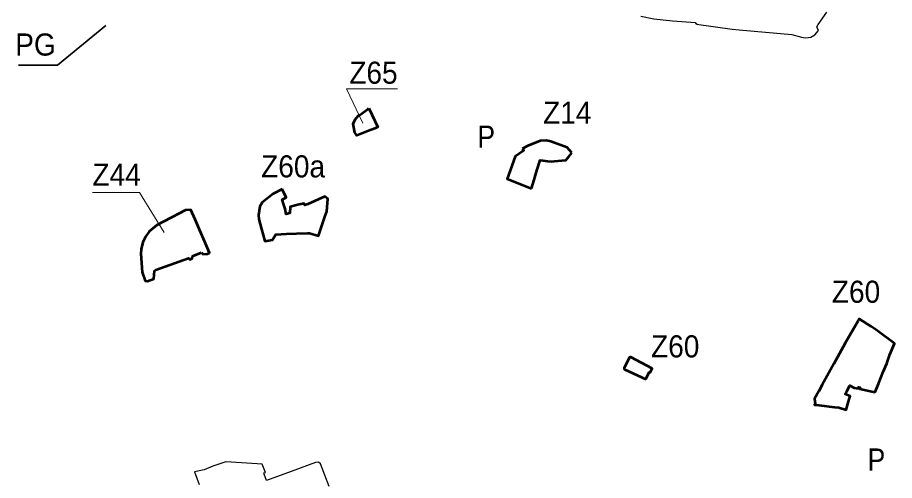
# Model space of a CAD drawing. Extents: x -650246 to -642674, y -1074280 to -1066767.
# Drawn here: x -647715 to -646763, y -1070690 to -1070187 of the extents above; entities that cross this region are included whole.
import ezdxf

# ---------------------------------------------------------------- set-up
doc = ezdxf.new("R2010")
doc.units = 0
doc.header["$LTSCALE"] = 9.6
for name, color, linetype, lineweight in [('42', 7, 'Continuous', 25), ('45', 7, 'Continuous', 53), ('46', 7, 'Continuous', 13), ('60', 7, 'Continuous', 35)]:
    doc.layers.add(name, color=color, linetype=linetype, lineweight=lineweight)

msp = doc.modelspace()

# ---------------------------------------------------------------- linework, layer by layer
at = {"layer": '42'}
for points in [[(-647038.31, -1070185.73), (-647024.2, -1070188.68), (-647003.89, -1070190.89), (-646978.73, -1070192.54), (-646978.72, -1070193.6), (-646977.7, -1070193.62), (-646977.7, -1070194.45), (-646938.98, -1070199.89), (-646931.25, -1070200.56), (-646874.04, -1070205.5), (-646863.66, -1070208.37), (-646859.54, -1070209.09), (-646853.67, -1070208.44), (-646849.15, -1070205.9), (-646845.3, -1070201.3), (-646847.17, -1070197.38), (-646845.76, -1070194.67), (-646836.06, -1070181.31)], [(-647377.04, -1070696.22), (-647386.39, -1070671.74), (-647388.31, -1070669.95), (-647391.74, -1070670.16), (-647418.28, -1070679.89), (-647444.78, -1070689.6), (-647447.31, -1070682.72), (-647447.76, -1070681.5), (-647446.22, -1070680.91), (-647447.58, -1070677.36), (-647449.69, -1070671.81), (-647455.17, -1070671.48), (-647489.21, -1070669.41), (-647496.64, -1070671.93), (-647503.3, -1070674.3), (-647512.51, -1070677.98), (-647523.27, -1070680.11), (-647518.19, -1070693.93)]]:
    msp.add_lwpolyline(points, dxfattribs=at)
at = {"layer": '45'}
for points in [[(-647333.87, -1070285.66), (-647324.11, -1070306.21), (-647324.94, -1070306.63), (-647327.18, -1070307.52), (-647333.97, -1070310.22), (-647346.97, -1070315.05), (-647349, -1070312), (-647350.67, -1070302.55), (-647348.677, -1070297.894), (-647345.27, -1070293.99), (-647343.9, -1070292.96), (-647337.56, -1070288.43), (-647334.91, -1070286.51)], [(-647333.87, -1070285.66), (-647324.11, -1070306.21), (-647324.94, -1070306.63), (-647327.18, -1070307.52), (-647333.97, -1070310.22), (-647346.97, -1070315.05), (-647349, -1070312), (-647350.67, -1070302.55), (-647348.677, -1070297.894), (-647345.27, -1070293.99), (-647343.9, -1070292.96), (-647337.56, -1070288.43), (-647334.91, -1070286.51)], [(-647427.8, -1070373.32), (-647437.76, -1070378.66), (-647449.69, -1070387.83), (-647452.17, -1070392.38), (-647453.71, -1070401.81), (-647453.35, -1070406.09), (-647450.51, -1070416.96), (-647446.93, -1070429.99), (-647438.45, -1070428.47), (-647434.85, -1070422.64), (-647423.38, -1070421.87), (-647412.51, -1070421.5), (-647400.41, -1070421.08), (-647398.21, -1070421.15), (-647388.6, -1070424.24), (-647381.11, -1070402.45), (-647379.3, -1070397.57), (-647378.49, -1070383.91), (-647381.65, -1070381.45), (-647400.22, -1070389.64), (-647403.27, -1070390.91), (-647404, -1070388.84), (-647409.36, -1070390.24), (-647419.08, -1070392.52), (-647419.68, -1070399.59), (-647423.58, -1070400.59), (-647424.54, -1070394.78), (-647425.99, -1070390.47), (-647427.96, -1070384.64), (-647423.57, -1070382.64)], [(-647427.8, -1070373.32), (-647437.76, -1070378.66), (-647449.69, -1070387.83), (-647452.17, -1070392.38), (-647453.71, -1070401.81), (-647453.35, -1070406.09), (-647450.51, -1070416.96), (-647446.93, -1070429.99), (-647438.45, -1070428.47), (-647434.85, -1070422.64), (-647423.38, -1070421.87), (-647412.51, -1070421.5), (-647400.41, -1070421.08), (-647398.21, -1070421.15), (-647388.6, -1070424.24), (-647381.11, -1070402.45), (-647379.3, -1070397.57), (-647378.49, -1070383.91), (-647381.65, -1070381.45), (-647400.22, -1070389.64), (-647403.27, -1070390.91), (-647404, -1070388.84), (-647409.36, -1070390.24), (-647419.08, -1070392.52), (-647419.68, -1070399.59), (-647423.58, -1070400.59), (-647424.54, -1070394.78), (-647425.99, -1070390.47), (-647427.96, -1070384.64), (-647423.57, -1070382.64)], [(-647515.73, -1070442.32), (-647514.23, -1070444.18), (-647509.22, -1070443.62), (-647506.95, -1070442.71), (-647522.54, -1070406.51), (-647527.1, -1070395.72), (-647533.1, -1070396.26), (-647564.01, -1070412.59), (-647572.37, -1070419.41), (-647576.48, -1070425.09), (-647579.22, -1070431.05), (-647581.04, -1070438.4), (-647581.54, -1070443.7), (-647580.1, -1070463.69), (-647576.92, -1070473), (-647574.28, -1070473.46), (-647567.32, -1070470.66), (-647566.55, -1070462.22), (-647565.11, -1070461.12), (-647529.74, -1070448.27), (-647528.28, -1070449.87), (-647525.54, -1070448.89), (-647525.45, -1070446.21)], [(-647515.73, -1070442.32), (-647514.23, -1070444.18), (-647509.22, -1070443.62), (-647506.95, -1070442.71), (-647522.54, -1070406.51), (-647527.1, -1070395.72), (-647533.1, -1070396.26), (-647564.01, -1070412.59), (-647572.37, -1070419.41), (-647576.48, -1070425.09), (-647579.22, -1070431.05), (-647581.04, -1070438.4), (-647581.54, -1070443.7), (-647580.1, -1070463.69), (-647576.92, -1070473), (-647574.28, -1070473.46), (-647567.32, -1070470.66), (-647566.55, -1070462.22), (-647565.11, -1070461.12), (-647529.74, -1070448.27), (-647528.28, -1070449.87), (-647525.54, -1070448.89), (-647525.45, -1070446.21)], [(-646802.19, -1070516.26), (-646816.42, -1070540.49), (-646828.45, -1070562.89), (-646841.16, -1070585.79), (-646844.76, -1070592.54), (-646849.72, -1070600.98), (-646848.99, -1070606.28), (-646849.59, -1070607.4), (-646844.96, -1070607.98), (-646827.88, -1070610.12), (-646822.99, -1070610.51), (-646815.05, -1070613.14), (-646812.5, -1070603.78), (-646811.5, -1070600.29), (-646810.82, -1070598.23), (-646816.11, -1070595.8), (-646814.52, -1070592.78), (-646811.06, -1070586.67), (-646806.41, -1070589), (-646802.06, -1070589.93), (-646801.73, -1070588.37), (-646800.13, -1070588.71), (-646800.47, -1070590.28), (-646784.18, -1070593.76), (-646784, -1070593.34), (-646783.59, -1070593.52), (-646779.9, -1070584.92), (-646774.91, -1070571.88), (-646771.17, -1070562.7), (-646767.63, -1070553.09), (-646762.71, -1070540.85), (-646782.63, -1070526.02), (-646788, -1070522.49), (-646800.94, -1070514.04)], [(-646802.19, -1070516.26), (-646816.42, -1070540.49), (-646828.45, -1070562.89), (-646841.16, -1070585.79), (-646844.76, -1070592.54), (-646849.72, -1070600.98), (-646848.99, -1070606.28), (-646849.59, -1070607.4), (-646844.96, -1070607.98), (-646827.88, -1070610.12), (-646822.99, -1070610.51), (-646815.05, -1070613.14), (-646812.5, -1070603.78), (-646811.5, -1070600.29), (-646810.82, -1070598.23), (-646816.11, -1070595.8), (-646814.52, -1070592.78), (-646811.06, -1070586.67), (-646806.41, -1070589), (-646802.06, -1070589.93), (-646801.73, -1070588.37), (-646800.13, -1070588.71), (-646800.47, -1070590.28), (-646784.18, -1070593.76), (-646784, -1070593.34), (-646783.59, -1070593.52), (-646779.9, -1070584.92), (-646774.91, -1070571.88), (-646771.17, -1070562.7), (-646767.63, -1070553.09), (-646762.71, -1070540.85), (-646782.63, -1070526.02), (-646788, -1070522.49), (-646800.94, -1070514.04)], [(-647032.738, -1070579.83), (-647029.168, -1070572.13), (-647028.248, -1070572.63), (-647025.868, -1070568.26), (-647049.248, -1070555.64), (-647050.098, -1070555.74), (-647050.868, -1070556.59), (-647052.498, -1070559.7), (-647056.518, -1070567.41), (-647056.528, -1070568.32), (-647055.518, -1070569.07)]]:
    msp.add_lwpolyline(points, close=True, dxfattribs=at)
for points in [[(-647113.37, -1070333.96), (-647118.28, -1070328.29), (-647135.94, -1070321.54), (-647140.83, -1070320.47), (-647147.66, -1070321.04), (-647161.17, -1070326.29), (-647167.03, -1070329.81)], [(-647167.03, -1070329.81), (-647165.36, -1070331.59), (-647174.81, -1070338.01), (-647183.55, -1070362.35), (-647156.9, -1070372.69)], [(-647156.9, -1070372.69), (-647154.31, -1070363.46), (-647151.09, -1070353.15), (-647147.6, -1070341.95), (-647144.57, -1070342.42), (-647139.84, -1070343.16), (-647135.62, -1070343.32), (-647132.49, -1070342.91)], [(-647132.49, -1070342.91), (-647119.88, -1070342.1), (-647116.03, -1070337.68), (-647113.37, -1070333.96)]]:
    msp.add_lwpolyline(points, dxfattribs=at)
at = {"layer": '46'}
for points in [[(-647302.639, -1070264.673), (-647358.031, -1070264.673), (-647340.193, -1070301.786)], [(-647302.639, -1070264.673), (-647358.031, -1070264.673), (-647340.193, -1070301.786)], [(-647634.056, -1070376.951), (-647582.888, -1070376.951), (-647556.111, -1070420.553)], [(-647634.056, -1070376.951), (-647582.888, -1070376.951), (-647556.111, -1070420.553)]]:
    msp.add_lwpolyline(points, dxfattribs=at)
at = {"layer": '60'}
msp.add_lwpolyline([(-647714.329, -1070238.836), (-647672.08, -1070238.836), (-647619.504, -1070195.616)], dxfattribs=at)
msp.add_lwpolyline([(-647714.329, -1070238.836), (-647672.08, -1070238.836), (-647619.504, -1070195.616)], dxfattribs=at)

# ---------------------------------------------------------------- texts
at = {"layer": '46', "width": 0.95}
for s, p in [('Z65', (-647355.018, -1070259.014)), ('Z65', (-647355.018, -1070259.014)), ('Z14', (-647144.477, -1070302.522)), ('Z60a', (-647450.804, -1070360.702)), ('Z44', (-647634.087, -1070369.724)), ('Z44', (-647634.087, -1070369.724)), ('Z60', (-646830.725, -1070496.795)), ('Z60', (-647027.184, -1070556.06))]:
    msp.add_text(s, height=24, dxfattribs=at).set_placement(p)
at = {"layer": '60'}
for s, width, p in [('PG', 0.95, (-647717.94, -1070228.451)), ('PG', 0.95, (-647717.94, -1070228.451)), ('P', 0.9, (-647215.907, -1070328.431)), ('P', 0.9, (-647215.907, -1070328.431)), ('P', 0.9, (-646791.982, -1070678.937)), ('P', 0.9, (-646791.982, -1070678.937))]:
    msp.add_text(s, height=24, dxfattribs=dict(at, width=width)).set_placement(p)

doc.saveas('drawing.dxf')
